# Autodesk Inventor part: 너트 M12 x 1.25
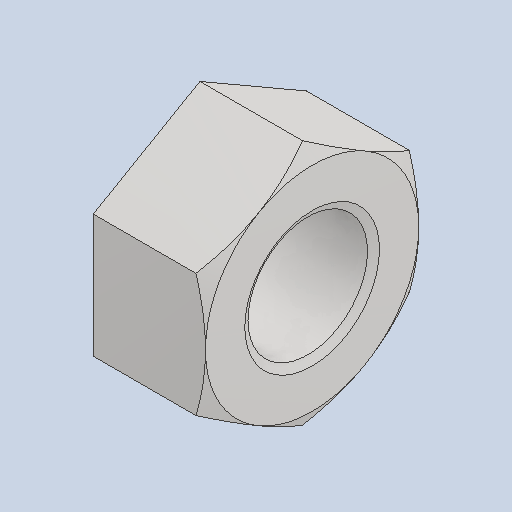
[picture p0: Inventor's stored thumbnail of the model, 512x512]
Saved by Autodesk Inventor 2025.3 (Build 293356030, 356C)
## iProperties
Created: 2025-08
Part Number: 너트 M12 x 1.25
Material: 스테인리스강
Description: 6각 너트
Document SubType Name: Modeling
Designer: user
Density: 8.08 g/cm^3
Appearance: 기본값
Author: jhkim
Sending System: Autodesk Inventor 2026
Preprocessor: ST-DEVELOPER v20.1
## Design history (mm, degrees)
sketch "스케치1"
  geometry: 1 further point
  constraints: 1 other
feature "Solid1"
node "솔리드1"
